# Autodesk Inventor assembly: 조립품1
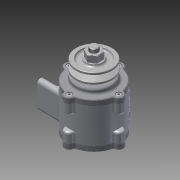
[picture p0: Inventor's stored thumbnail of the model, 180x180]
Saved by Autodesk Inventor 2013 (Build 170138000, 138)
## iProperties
Created: 2015-03
Part Number: 조립품1
Document SubType Name: Assembly
Designer: cad10
Author: cad10
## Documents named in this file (11)
- C:\Documents and Settings\cad10\바탕 화면\450306V1038\조립품1.iam
- C:\Documents and Settings\cad10\바탕 화면\450306V1038\베어링 6204.ipt
- C:\Documents and Settings\cad10\바탕 화면\450306V1038\오일실.ipt
- C:\Documents and Settings\cad10\바탕 화면\450306V1038\축.ipt
- C:\Documents and Settings\cad10\바탕 화면\450306V1038\커버2.ipt
- C:\Documents and Settings\cad10\바탕 화면\450306V1038\커버.ipt
- C:\Documents and Settings\cad10\바탕 화면\450306V1038\키(4 x 4 x 12).ipt
- C:\Documents and Settings\cad10\바탕 화면\450306V1038\M 4 x 12.ipt
- C:\Documents and Settings\cad10\바탕 화면\450306V1038\V벨트풀리.ipt
- C:\Documents and Settings\cad10\바탕 화면\450306V1038\너트 M12x1.25.ipt
- C:\Documents and Settings\cad10\바탕 화면\450306V1038\본체.ipt
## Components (14 placed, 6 different names)
1. KS B 2023 6204 - 20 x 47 x 14:1
2. KS B 2804 D D - 20 32 8:1
3. KS B 1311 (I) 4 x 4 x 12:1
4. KS B 1003 - 미터 M 4 x 12:1
5. 그루브 풀리1:1
6. KS B 1012 클래스 1 일반 - 미터 M12x1.25:1
7. KS B 1003 - 미터 M 4 x 12:2
8. KS B 1003 - 미터 M 4 x 12:3
9. KS B 1003 - 미터 M 4 x 12:4
10. KS B 1003 - 미터 M 4 x 12:5
11. KS B 1003 - 미터 M 4 x 12:7
12. KS B 1003 - 미터 M 4 x 12:8
13. KS B 1003 - 미터 M 4 x 12:9
14. KS B 2023 6204 - 20 x 47 x 14:2
